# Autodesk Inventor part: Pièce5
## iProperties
Shininess: 64.0
Length Units: 11269
Angle Units: 11279
Time Units: 11290
Mass Units: 11283
Length Display Precision: 3
Angle Display Precision: 2
Compacted: True
Part Number: Pièce5
Document SubType Name: Modeling
Created: 2004-06
Material: Par défaut
Designer: administrateur
Density: 0.0
Volumn: 0.0
Area: 0.0
PropertySet Name: Model Information
Control State: 0
Master: False
Checked Out: False
Author: administrateur
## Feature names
1. Extrusion1
2. Balayage1
3. Extrusion2
4. Extrusion3
5. Balayage2
6. Extrusion4
7. Balayage3
